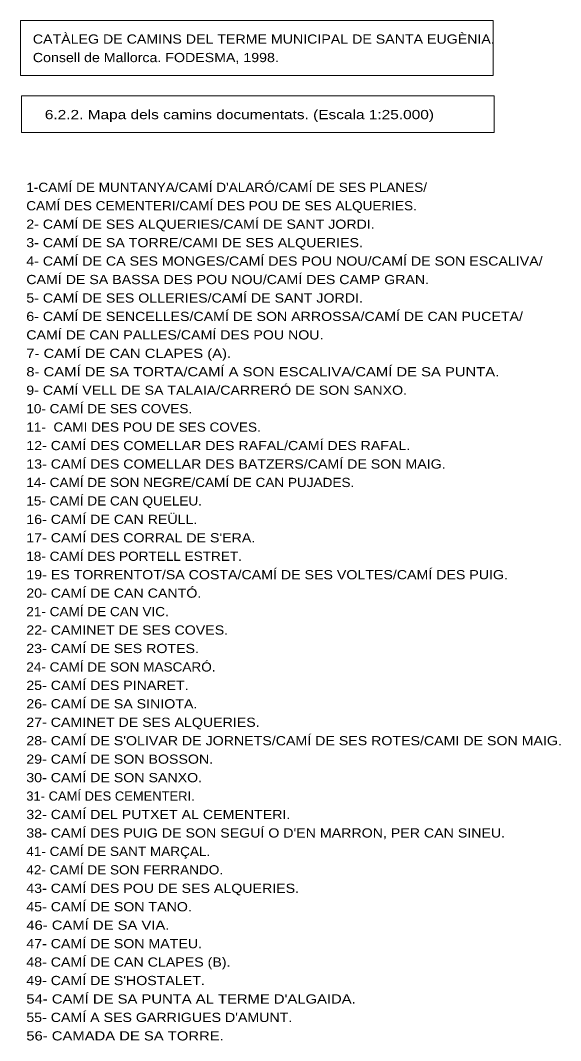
# Model space of a CAD drawing. Extents: x 476989 to 498418, y 4381813 to 4416555.
# Drawn here: x 480312 to 483239, y 4383387 to 4388918 of the extents above; entities that cross this region are included whole.
import ezdxf
from ezdxf.enums import TextEntityAlignment as Align

# ---------------------------------------------------------------- set-up
doc = ezdxf.new("R2010")
doc.units = 0
doc.header["$LTSCALE"] = 20
doc.layers.add('13', color=7, linetype='Continuous', lineweight=13)

msp = doc.modelspace()

# ---------------------------------------------------------------- linework, layer by layer
at = {"layer": '13'}
for points in [[(480311.63, 4388917.52), (482873.59, 4388917.52), (482873.59, 4388618.76), (480311.63, 4388618.76)], [(480316.85, 4388508.69), (482878.81, 4388508.69), (482878.81, 4388309.52), (480316.85, 4388309.52)]]:
    msp.add_lwpolyline(points, close=True, dxfattribs=at)

# ---------------------------------------------------------------- texts
for s, width, p in [('CATÀLEG DE CAMINS DEL TERME MUNICIPAL DE SANTA EUGÈNIA.', 1.15, (480379.02, 4388791.28)), ('Consell de Mallorca. FODESMA, 1998.', 1.15, (480379.02, 4388691.28)), ("1-CAMÍ DE MUNTANYA/CAMÍ D'ALARÓ/CAMÍ DE SES PLANES/", 1.1, (480343.57, 4387987.83)), ('CAMÍ DES CEMENTERI/CAMÍ DES POU DE SES ALQUERIES.', 1.1, (480343.57, 4387887.83)), ('2- CAMÍ DE SES ALQUERIES/CAMÍ DE SANT JORDI.', 1.15, (480343.57, 4387787.83)), ('3- CAMÍ DE SA TORRE/CAMI DE SES ALQUERIES.', 1.15, (480343.57, 4387687.83)), ('4- CAMÍ DE CA SES MONGES/CAMÍ DES POU NOU/CAMÍ DE SON ESCALIVA/', 1.15, (480343.57, 4387587.83)), ('CAMÍ DE SA BASSA DES POU NOU/CAMÍ DES CAMP GRAN.', 1.15, (480343.57, 4387487.83)), ('5- CAMÍ DE SES OLLERIES/CAMÍ DE SANT JORDI.', 1.15, (480343.57, 4387387.83)), ('6- CAMÍ DE SENCELLES/CAMÍ DE SON ARROSSA/CAMÍ DE CAN PUCETA/', 1.15, (480343.57, 4387287.83)), ('CAMÍ DE CAN PALLES/CAMÍ DES POU NOU.', 1.15, (480343.57, 4387187.83)), ('7- CAMÍ DE CAN CLAPES (A).', 1.2, (480343.57, 4387087.83)), ('8- CAMÍ DE SA TORTA/CAMÍ A SON ESCALIVA/CAMÍ DE SA PUNTA.', 1.2, (480343.57, 4386987.83)), ('9- CAMÍ VELL DE SA TALAIA/CARRERÓ DE SON SANXO.', 1.15, (480343.57, 4386887.83)), ('10- CAMÍ DE SES COVES.', 1.1, (480343.57, 4386787.83)), ('11-  CAMI DES POU DE SES COVES.', 1.1, (480343.57, 4386687.83)), ('12- CAMÍ DES COMELLAR DES RAFAL/CAMÍ DES RAFAL.', 1.15, (480343.57, 4386587.83)), ('13- CAMÍ DES COMELLAR DES BATZERS/CAMÍ DE SON MAIG.', 1.15, (480343.57, 4386487.83)), ('14- CAMÍ DE SON NEGRE/CAMÍ DE CAN PUJADES.', 1.1, (480343.57, 4386387.83)), ('15- CAMÍ DE CAN QUELEU.', 1.1, (480343.57, 4386287.83)), ('16- CAMÍ DE CAN REÜLL.', 1.15, (480343.57, 4386187.83)), ("17- CAMÍ DES CORRAL DE S'ERA.", 1.15, (480343.57, 4386087.83)), ('18- CAMÍ DES PORTELL ESTRET.', 1.1, (480343.57, 4385987.83)), ('19- ES TORRENTOT/SA COSTA/CAMÍ DE SES VOLTES/CAMÍ DES PUIG.', 1.15, (480343.57, 4385887.83)), ('20- CAMÍ DE CAN CANTÓ.', 1.15, (480343.57, 4385787.83)), ('21- CAMÍ DE CAN VIC.', 1.1, (480343.57, 4385687.83)), ('22- CAMINET DE SES COVES.', 1.15, (480343.57, 4385587.83)), ('23- CAMÍ DE SES ROTES.', 1.15, (480343.57, 4385487.83)), ('24- CAMÍ DE SON MASCARÓ.', 1.1, (480343.57, 4385387.83)), ('25- CAMÍ DES PINARET.', 1.15, (480343.57, 4385287.83)), ('26- CAMÍ DE SA SINIOTA.', 1.15, (480343.57, 4385187.83)), ('27- CAMINET DE SES ALQUERIES.', 1.15, (480343.57, 4385087.83)), ("28- CAMÍ DE S'OLIVAR DE JORNETS/CAMÍ DE SES ROTES/CAMI DE SON MAIG.", 1.15, (480343.57, 4384987.83)), ('29- CAMÍ DE SON BOSSON.', 1.15, (480343.57, 4384887.83)), ('30- CAMÍ DE SON SANXO.', 1.15, (480343.57, 4384787.83)), ('31- CAMÍ DES CEMENTERI.', 1.05, (480343.57, 4384687.83)), ('32- CAMÍ DEL PUTXET AL CEMENTERI.', 1.15, (480343.57, 4384587.83)), ("38- CAMÍ DES PUIG DE SON SEGUÍ O D'EN MARRON, PER CAN SINEU.", 1.15, (480343.57, 4384487.83)), ('41- CAMÍ DE SANT MARÇAL.', 1.1, (480343.57, 4384387.83)), ('42- CAMÍ DE SON FERRANDO.', 1.1, (480343.57, 4384287.83)), ('43- CAMÍ DES POU DE SES ALQUERIES.', 1.15, (480343.57, 4384187.83)), ('45- CAMÍ DE SON TANO.', 1.15, (480343.57, 4384087.83)), ('46- CAMÍ DE SA VIA.', 1.2, (480343.57, 4383987.83)), ('47- CAMÍ DE SON MATEU.', 1.15, (480343.57, 4383887.83)), ('48- CAMÍ DE CAN CLAPES (B).', 1.15, (480343.57, 4383787.83)), ("49- CAMÍ DE S'HOSTALET.", 1.15, (480343.57, 4383687.83)), ("54- CAMÍ DE SA PUNTA AL TERME D'ALGAIDA.", 1.2, (480343.57, 4383587.83)), ("55- CAMÍ A SES GARRIGUES D'AMUNT.", 1.15, (480343.57, 4383487.83)), ('56- CAMADA DE SA TORRE.', 1.2, (480343.57, 4383387.83))]:
    msp.add_text(s, height=50, dxfattribs=dict(at, width=width)).set_placement(p)
at = {"layer": '13', "width": 1.25}
msp.add_text('6.2.2. Mapa dels camins documentats. (Escala 1:25.000)', height=50, dxfattribs=at).set_placement((481498.6, 4388382.09), align=Align.CENTER)

doc.saveas('drawing.dxf')
